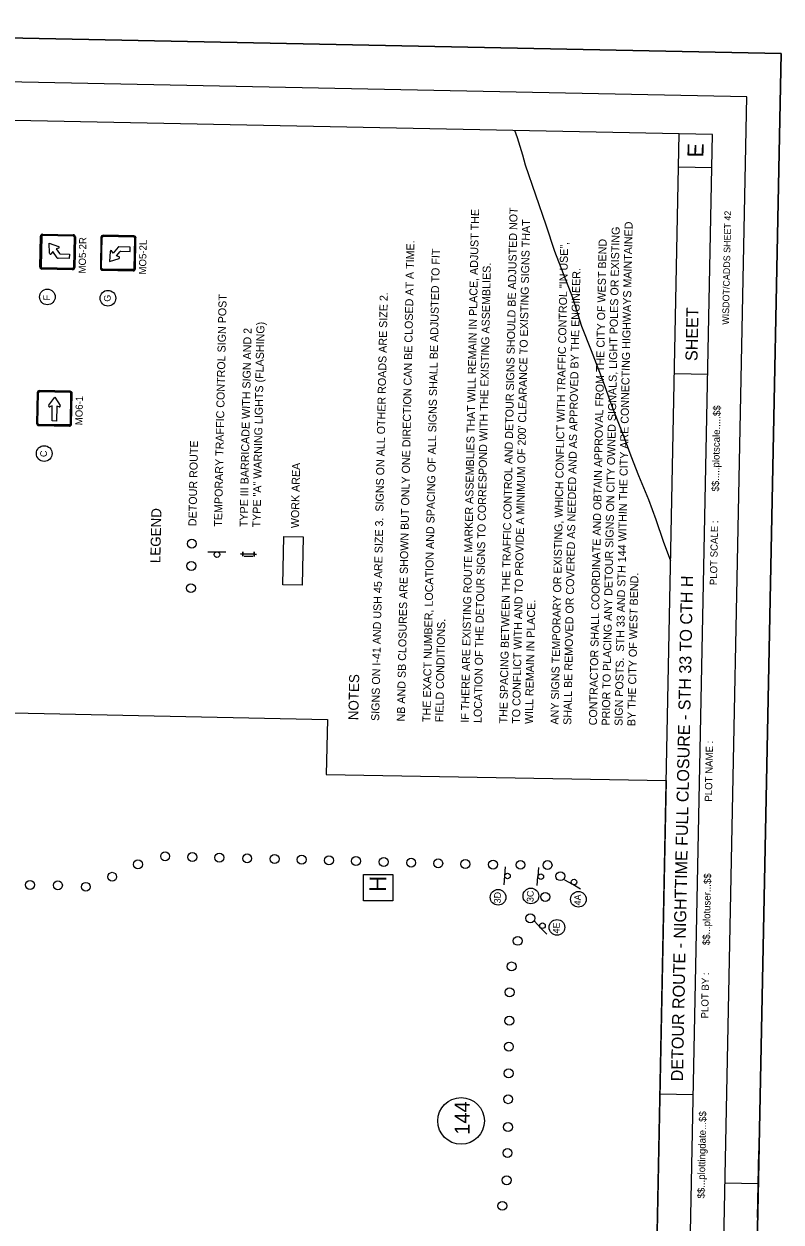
# Model space of a CAD drawing. Extents: x 345549 to 379569, y 127949 to 230467.
# Drawn here: x 362548 to 379569, y 203528 to 230467 of the extents above; entities that cross this region are included whole.
import ezdxf

# ---------------------------------------------------------------- set-up
doc = ezdxf.new("R2010")
doc.units = 0
for name, color, linetype in [('CA-TEXT', 7, 'Continuous'), ('CE-TOPO-CONC-SLAB', 7, 'Continuous'), ('Level 1', 7, 'Continuous'), ('P_MISC_NoPlot', 7, 'Continuous'), ('P_RDWY_Text', 7, 'Continuous'), ('P_SGN_Cell', 7, 'Continuous'), ('P_TC', 7, 'Continuous'), ('PLT_Sheet_Border', 7, 'Continuous'), ('PLT_Sheet_Info', 7, 'Continuous'), ('SIGNS-POLES', 7, 'Continuous')]:
    doc.layers.add(name, color=color, linetype=linetype)

msp = doc.modelspace()

# ---------------------------------------------------------------- linework, layer by layer
at = {"layer": 'CA-TEXT'}
for p, q in [((370504, 211059), (370504, 211059)), ((372375, 205801), (372375, 205801))]:
    msp.add_line(p, q, dxfattribs=at)
msp.add_lwpolyline([(370839, 210751), (370183, 210753), (370185, 211342), (370841, 211339)], close=True, dxfattribs=at)
for centre, radius in [((363074, 224329), 176), ((364436, 224301), 176), ((363003, 220808), 176), ((373208, 210829), 176), ((373945, 210859), 176), ((375013, 210784), 176), ((374532, 210154), 176), ((372375, 205801), 524)]:
    msp.add_circle(centre, radius, dxfattribs=at)
at = {"layer": 'CE-TOPO-CONC-SLAB'}
for centre in [(366322, 218781), (366312, 218281), (366302, 217781), (365722, 211751), (366333, 211734), (366941, 211722), (367566, 211704), (368183, 211692), (368791, 211677), (369405, 211660), (370012, 211645), (365111, 211570), (370637, 211624), (371254, 211608), (371862, 211593), (372470, 211577), (373095, 211565), (373712, 211560), (374320, 211554), (362684, 211108), (364532, 211291), (374609, 211304), (363311, 211100), (363939, 211066), (374268, 210838), (373933, 210357), (373650, 209850), (373511, 209275), (373466, 208694), (373462, 208054), (373450, 207472), (373447, 206870), (373434, 206289), (373431, 205663), (373419, 205081), (373402, 204467), (373304, 203892)]:
    msp.add_circle(centre, 100, dxfattribs=at)
at = {"layer": 'Level 1'}
for points in [[(375089, 223667), (374885, 224310), (374481, 225351), (374287, 225940), (373824, 227294), (373763, 227520), (373642, 227908), (373585, 228070)], [(376929, 218831), (376765, 219317), (376594, 219769), (376374, 220308), (376203, 220748), (376044, 221174), (375775, 221864), (375604, 222328), (375531, 222529), (375311, 223118), (375089, 223667)], [(377089, 218388), (376929, 218831)]]:
    msp.add_lwpolyline(points, dxfattribs=at)
at = {"layer": 'P_MISC_NoPlot'}
msp.add_lwpolyline([(347087, 181344), (347770, 215283), (369369, 214831), (369345, 213590), (376990, 213459), (376331, 180755)], close=True, dxfattribs=at)
at = {"layer": 'P_RDWY_Text'}
msp.add_lwpolyline([(345549, 179477), (346576, 230467), (379569, 229803), (378542, 178813)], close=True, dxfattribs=at)
at = {"layer": 'P_SGN_Cell'}
for p, q in [((362904, 225005), (362918, 225694)), ((362931, 225694), (362917, 225005)), ((362947, 225694), (362933, 225005)), ((363656, 225699), (362967, 225713)), ((362968, 225742), (363657, 225729)), ((363657, 225715), (362968, 225729)), ((363123, 225311), (363114, 225536)), ((363114, 225536), (363328, 225464)), ((363676, 225679), (363662, 224990)), ((363692, 225679), (363678, 224990)), ((363705, 225678), (363691, 224989)), ((364280, 225667), (364266, 224978)), ((364279, 224978), (364293, 225667)), ((364295, 224977), (364309, 225666)), ((365018, 225672), (364329, 225685)), ((365019, 225701), (364330, 225715)), ((365019, 225688), (364330, 225702)), ((365024, 224963), (365038, 225652)), ((365040, 224962), (365054, 225651)), ((365053, 224962), (365067, 225651)), ((363194, 225348), (363159, 225300)), ((363297, 225210), (363194, 225348)), ((363328, 225427), (363273, 225407)), ((363273, 225407), (363349, 225305)), ((363362, 225298), (363569, 225294)), ((363569, 225294), (363567, 225195)), ((364487, 225353), (364468, 225128)), ((364556, 225313), (364523, 225362)), ((364664, 225447), (364556, 225313)), ((364632, 225251), (364713, 225350)), ((364687, 225228), (364632, 225251)), ((364935, 225450), (364683, 225455)), ((364726, 225356), (364933, 225352)), ((364933, 225352), (364935, 225450)), ((363641, 224954), (362952, 224968)), ((363641, 224941), (362952, 224955)), ((363642, 224971), (362953, 224985)), ((363567, 225195), (363315, 225200)), ((365004, 224943), (364315, 224957)), ((364468, 225128), (364685, 225191)), ((365003, 224927), (364314, 224941)), ((364314, 224928), (365003, 224914)), ((362847, 222174), (362833, 221485)), ((362846, 221485), (362860, 222174)), ((362862, 221484), (362876, 222173)), ((363585, 222179), (362896, 222193)), ((363586, 222208), (362897, 222222)), ((363586, 222195), (362897, 222209)), ((363107, 221892), (363239, 222075)), ((363239, 222075), (363363, 221887)), ((363591, 221470), (363605, 222159)), ((363607, 221469), (363621, 222158)), ((363620, 221469), (363634, 222158)), ((363185, 221877), (363128, 221861)), ((363179, 221541), (363185, 221877)), ((363284, 221875), (363277, 221539)), ((363340, 221857), (363284, 221875)), ((363570, 221434), (362881, 221448)), ((363571, 221450), (362882, 221464)), ((363277, 221539), (363179, 221541)), ((362881, 221435), (363570, 221421))]:
    msp.add_line(p, q, dxfattribs=at)
for centre, radius, start, end in [((362967, 225693), 49.2, 88.8462, 178.8462), ((362967, 225693), 49.2, 144.5056, 178.8462), ((362967, 225693), 36.1, 88.8462, 178.8462), ((362967, 225693), 49.2, 88.8462, 113.5578), ((362967, 225693), 19.7, 88.8462, 178.8462), ((363656, 225679), 19.7, 358.8462, 88.8462), ((363656, 225679), 49.2, 358.8462, 88.8462), ((363656, 225679), 36.1, 358.8462, 88.8462), ((364329, 225666), 49.2, 88.8462, 178.8462), ((364329, 225666), 36.1, 88.8462, 178.8462), ((364329, 225666), 19.7, 88.8462, 178.8462), ((365018, 225652), 19.7, 358.8462, 88.8462), ((365018, 225652), 49.2, 358.8462, 88.8462), ((365018, 225652), 36.1, 358.8462, 88.8462), ((363143, 225312), 19.7, 182.3166, 323.6488), ((363321, 225445), 19.7, 290.0436, 71.3759), ((363362, 225314), 16.4, 216.8461, 268.8462), ((364506, 225351), 19.7, 34.0436, 175.3759), ((364682, 225432), 23, 88.8462, 140.8466), ((364679, 225210), 19.7, 286.3166, 67.6488), ((364725, 225339), 16.4, 88.8462, 140.8463), ((362953, 225004), 49.2, 178.8462, 268.8462), ((362953, 225004), 36.1, 178.8462, 268.8462), ((362953, 225004), 19.7, 178.8462, 268.8462), ((363316, 225223), 23, 216.8459, 268.8462), ((363642, 224990), 36.1, 268.8462, 358.8462), ((363642, 224990), 49.2, 268.8462, 358.8462), ((363642, 224990), 19.7, 268.8462, 358.8462), ((364315, 224977), 49.2, 178.8462, 268.8462), ((364315, 224977), 49.2, 178.8462, 213.1868), ((364315, 224977), 36.1, 178.8462, 268.8462), ((364315, 224977), 19.7, 178.8462, 268.8462), ((365004, 224963), 36.1, 268.8462, 358.8462), ((365004, 224963), 49.2, 268.8462, 358.8462), ((365004, 224963), 19.7, 268.8462, 358.8462), ((364315, 224977), 49.2, 244.1347, 268.8462), ((362896, 222173), 49.2, 88.8462, 178.8462), ((362896, 222173), 36.1, 88.8462, 178.8462), ((362896, 222173), 19.7, 88.8462, 178.8462), ((363585, 222159), 19.7, 358.8462, 88.8462), ((363585, 222159), 49.2, 358.8462, 88.8462), ((363585, 222159), 36.1, 358.8462, 88.8462), ((363123, 221880), 19.7, 144.3166, 285.6488), ((363346, 221876), 19.7, 252.0436, 33.3759), ((362882, 221484), 49.2, 178.8462, 268.8462), ((362882, 221484), 36.1, 178.8462, 268.8462), ((362882, 221484), 19.7, 178.8462, 268.8462), ((363571, 221470), 36.1, 268.8462, 358.8462), ((363571, 221470), 49.2, 268.8462, 358.8462), ((363571, 221470), 19.7, 268.8462, 358.8462), ((362882, 221484), 49.2, 239.4497, 268.8462)]:
    msp.add_arc(centre, radius, start, end, dxfattribs=at)
at = {"layer": 'P_TC'}
for p, q in [((367468, 218548), (367417, 218549)), ((367417, 218549), (367468, 218548)), ((367468, 218548), (367467, 218497)), ((367467, 218497), (367468, 218548)), ((367468, 218548), (367469, 218599)), ((367469, 218599), (367468, 218548)), ((367723, 218543), (367468, 218548)), ((367692, 218492), (367497, 218496)), ((367723, 218543), (367722, 218492)), ((367722, 218492), (367723, 218543)), ((367724, 218594), (367723, 218543)), ((367723, 218543), (367724, 218594)), ((367723, 218543), (367774, 218541)), ((367774, 218541), (367723, 218543))]:
    msp.add_line(p, q, dxfattribs=at)
msp.add_lwpolyline([(368370, 217854), (368392, 218945), (368827, 218936), (368805, 217845)], close=True, dxfattribs=at)
at = {"layer": 'PLT_Sheet_Border'}
for points in [[(378542, 178813), (379569, 229803), (346576, 230467), (345549, 179477)], [(377800, 179188), (378799, 228828), (347306, 229462), (346306, 179822)]]:
    msp.add_lwpolyline(points, close=True, dxfattribs=at)
at = {"layer": 'PLT_Sheet_Info'}
for p, q in [((379569, 229803), (378070, 229833)), ((379539, 228303), (379569, 229803)), ((378032, 227981), (348038, 228585)), ((376331, 180755), (377282, 227996)), ((377081, 180740), (378032, 227981)), ((378017, 227231), (377267, 227246)), ((377924, 222582), (377174, 222597)), ((377597, 206385), (376847, 206400)), ((379042, 203633), (379072, 205132)), ((379057, 204383), (378307, 204398))]:
    msp.add_line(p, q, dxfattribs=at)
at = {"layer": 'SIGNS-POLES'}
for p, q in [((366681, 218600), (366884, 218599)), ((366885, 218598), (367088, 218595)), ((373358, 211311), (373374, 211513)), ((374107, 211296), (374123, 211498)), ((373342, 211108), (373356, 211310)), ((374090, 211093), (374105, 211295)), ((374886, 211117), (374710, 211217)), ((375063, 211015), (374887, 211115)), ((374163, 210145), (374023, 210291)), ((374304, 209998), (374163, 210143))]:
    msp.add_line(p, q, dxfattribs=at)
for centre in [(366887, 218535), (373420, 211309), (374169, 211293), (374915, 211172), (374206, 210190)]:
    msp.add_circle(centre, 62.6, dxfattribs=at)

# ---------------------------------------------------------------- texts
at = {"layer": 'CA-TEXT'}
for s, height, rotation, p in [('IF THERE ARE EXISTING ROUTE MARKER ASSEMBLIES THAT WILL REMAIN IN PLACE, ADJUST THE', 180, 88.8462, (372549, 214753)), ('THE SPACING BETWEEN THE TRAFFIC CONTROL AND DETOUR SIGNS SHOULD BE ADJUSTED NOT', 180, 88.8462, (373413, 214735)), ("TO CONFLICT WITH AND TO PROVIDE A MINIMUM OF 200' CLEARANCE TO EXISTING SIGNS THAT", 180, 88.8462, (373701, 214729)), ('PRIOR TO PLACING ANY DETOUR SIGNS ON CITY OWNED SIGNALS, LIGHT POLES OR EXISTING', 180, 88.8462, (375717, 214689)), ('SIGN POSTS.  STH 33 AND STH 144 WITHIN THE CITY ARE CONNECTING HIGHWAYS MAINTAINED ', 180, 88.8462, (376005, 214683)), ('NB AND SB CLOSURES ARE SHOWN BUT ONLY ONE DIRECTION CAN BE CLOSED AT A TIME.', 180, 88.8462, (371110, 214782)), ('ANY SIGNS TEMPORARY OR EXISTING, WHICH CONFLICT WITH TRAFFIC CONTROL "IN USE",', 180, 88.8462, (374565, 214712)), ('CONTRACTOR SHALL COORDINATE AND OBTAIN APPROVAL FROM THE CITY OF WEST BEND', 180, 88.8462, (375429, 214695)), ('THE EXACT NUMBER, LOCATION AND SPACING OF ALL SIGNS SHALL BE ADJUSTED TO FIT', 180, 88.8462, (371686, 214770)), ('LOCATION OF THE DETOUR SIGNS TO CORRESPOND WITH THE EXISTING ASSEMBLIES. ', 180, 88.8462, (372837, 214747)), ('SHALL BE REMOVED OR COVERED AS NEEDED AND AS APPROVED BY THE ENGINEER.', 180, 88.8462, (374853, 214706)), ('SIGNS ON I-41 AND USH 45 ARE SIZE 3.  SIGNS ON ALL OTHER ROADS ARE SIZE 2.', 180, 88.8462, (370534, 214793)), ('F', 150, 88.8468, (363133, 224249)), ('G', 150, 88.8468, (364495, 224221)), ('TEMPORARY TRAFFIC CONTROL SIGN POST', 180, 88.8468, (367000, 219162)), ('TYPE III BARRICADE WITH SIGN AND 2', 180, 88.8468, (367576, 219151)), ('TYPE "A" WARNING LIGHTS (FLASHING)', 180, 88.8468, (367864, 219145)), ('DETOUR ROUTE', 180, 88.8468, (366424, 219174)), ('C', 150, 88.8468, (363062, 220728)), ('WORK AREA', 180, 88.8468, (368728, 219128)), ('LEGEND', 225, 88.8468, (365613, 218341)), ('BY THE CITY OF WEST BEND.', 180, 88.8462, (376293, 214677)), ('WILL REMAIN IN PLACE.', 180, 88.8462, (373989, 214724)), ('FIELD CONDITIONS.', 180, 88.8462, (371974, 214764)), ('NOTES', 225, 88.8468, (370065, 214809)), ('H', 375, 89.767, (370691, 210952)), ('3D', 150, 88.8468, (373266, 210692)), ('3C', 150, 88.8468, (374003, 210721)), ('4A', 150, 88.8468, (375070, 210647)), ('4E', 150, 88.8468, (374589, 210017)), ('144', 337.5, 89.767, (372569, 205489))]:
    msp.add_text(s, height=height, rotation=rotation, dxfattribs=at).set_placement(p)
at = {"layer": 'P_SGN_Cell'}
for s, p in [('MO5-2R', (363936, 224854)), ('MO5-2L', (365293, 224831)), ('MO6-1', (363862, 221442))]:
    msp.add_text(s, height=162, rotation=88.8462, dxfattribs=at).set_placement(p)
at = {"layer": 'PLT_Sheet_Info'}
for s, height, p in [('E', 360, (377824, 227463)), ('WISDOT/CADDS SHEET 42', 150, (378396, 223703)), ('SHEET ', 270, (377690, 222887)), ('$$.....plotscale.....$$', 162, (378171, 219951)), ('PLOT SCALE : ', 162, (378128, 217846)), ('DETOUR ROUTE - NIGHTTIME FULL CLOSURE - STH 33 TO CTH H', 270, (377363, 206690)), ('PLOT NAME :                      ', 162, (378015, 212978)), ('$$...plotuser...$$', 162, (377965, 209753)), ('PLOT BY :', 162, (377932, 208104)), ('$$...plottingdate...$$', 162, (377850, 204055))]:
    msp.add_text(s, height=height, rotation=88.8462, dxfattribs=at).set_placement(p)

doc.saveas('drawing.dxf')
